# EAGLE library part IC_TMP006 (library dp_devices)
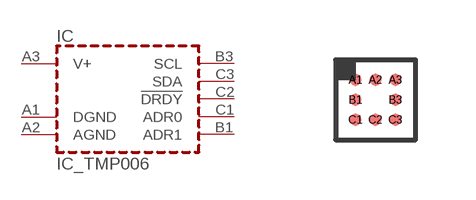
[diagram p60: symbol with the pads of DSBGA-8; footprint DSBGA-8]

Designator prefix IC

## IC_TMP006  [DSBGA-8]
A1  DGND  pwr
A2  AGND  pwr
A3  V+  pwr
B1  ADR1  in
B3  SCL  in
C1  ADR0  in
C2  !DRDY  out
C3  SDA

## Footprint DSBGA-8 (pad centres in mm)
smd 0.3 x 0.3: A1 -0.5,0.5; A2 0,0.5; A3 0.5,0.5; B1 -0.5,0; B3 0.5,0; C1 -0.5,-0.5; C2 0,-0.5; C3 0.5,-0.5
